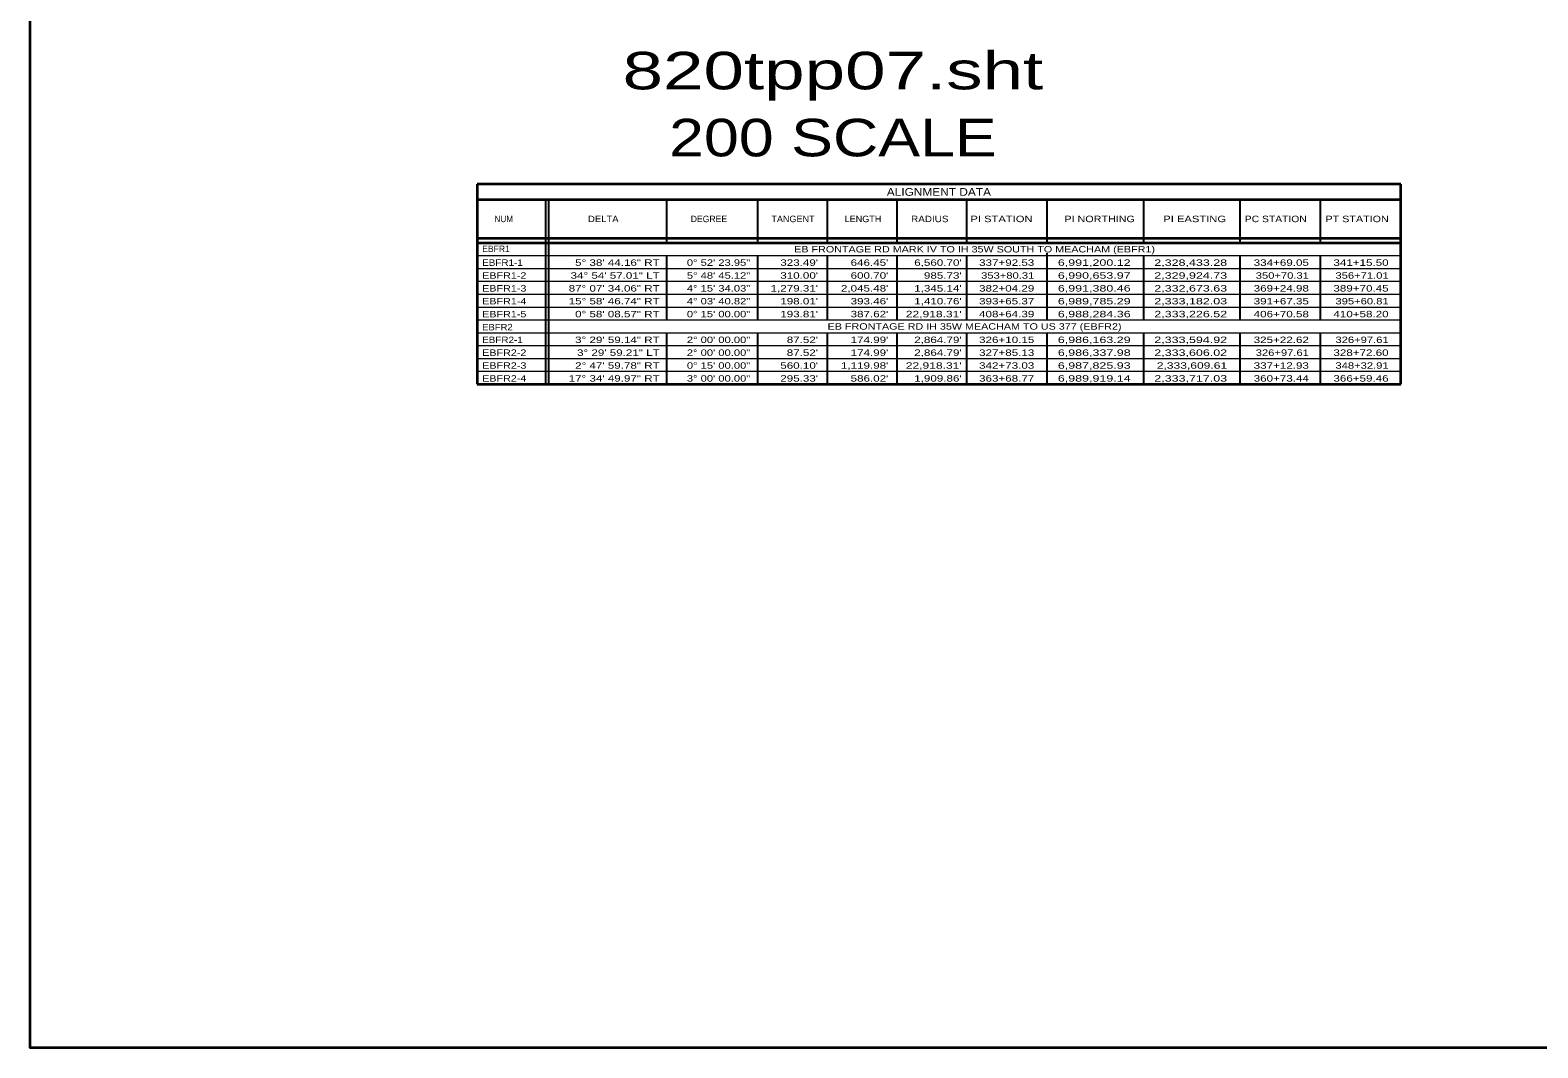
# Model space of a CAD drawing. Extents: x 1953053 to 1967065, y 7363860 to 7371201.
# Drawn here: x 1953053 to 1955866, y 7363860 to 7365759 of the extents above; entities that cross this region are included whole.
import ezdxf
from ezdxf.enums import TextEntityAlignment as Align

# ---------------------------------------------------------------- set-up
doc = ezdxf.new("R2010")
doc.units = 0
doc.header["$LTSCALE"] = 4.8
doc.layers.add('10', color=7, linetype='Continuous')
doc.layers.add('12', color=7, linetype='Continuous', lineweight=25)
doc.layers.add('62', color=7, linetype='Continuous', lineweight=35)

msp = doc.modelspace()

# ---------------------------------------------------------------- linework, layer by layer
at = {"layer": '12', "lineweight": 35}
for p, q in [((1955609.815, 7365471.266), (1953886.483, 7365471.266)), ((1953886.483, 7365471.266), (1953886.483, 7365098.133)), ((1955609.815, 7365098.133), (1955609.815, 7365471.266)), ((1953886.483, 7365442.466), (1955609.815, 7365442.466)), ((1953886.483, 7365370.466), (1955609.815, 7365370.466)), ((1953886.483, 7365362.133), (1955609.815, 7365362.133)), ((1953886.483, 7365098.133), (1955609.815, 7365098.133))]:
    msp.add_line(p, q, dxfattribs=at)
at = {"layer": '12'}
for p, q in [((1954014.328, 7365442.466), (1954014.328, 7365098.133)), ((1954019.815, 7365442.466), (1954019.815, 7365098.133)), ((1954239.815, 7365442.466), (1954239.815, 7365362.133)), ((1954409.815, 7365442.466), (1954409.815, 7365362.133)), ((1954539.815, 7365442.466), (1954539.815, 7365362.133)), ((1954669.815, 7365442.466), (1954669.815, 7365362.133)), ((1954799.815, 7365442.466), (1954799.815, 7365362.133)), ((1954949.815, 7365442.466), (1954949.815, 7365362.133)), ((1955129.815, 7365442.466), (1955129.815, 7365362.133)), ((1955309.815, 7365442.466), (1955309.815, 7365362.133)), ((1955459.815, 7365442.466), (1955459.815, 7365362.133)), ((1954014.328, 7365420.866), (1954014.328, 7365144.913)), ((1954239.815, 7365338.133), (1954239.815, 7365218.133)), ((1954409.815, 7365338.133), (1954409.815, 7365218.133)), ((1954539.815, 7365338.133), (1954539.815, 7365218.133)), ((1954669.815, 7365338.133), (1954669.815, 7365218.133)), ((1954799.815, 7365338.133), (1954799.815, 7365218.133)), ((1954949.815, 7365342.393), (1954949.815, 7365218.133)), ((1955129.815, 7365338.133), (1955129.815, 7365218.133)), ((1955309.815, 7365338.133), (1955309.815, 7365218.133)), ((1955459.815, 7365338.133), (1955459.815, 7365218.133)), ((1954239.815, 7365194.133), (1954239.815, 7365098.133)), ((1954409.815, 7365194.133), (1954409.815, 7365098.133)), ((1954539.815, 7365194.133), (1954539.815, 7365098.133)), ((1954669.815, 7365194.133), (1954669.815, 7365098.133)), ((1954799.815, 7365194.133), (1954799.815, 7365098.133)), ((1954949.815, 7365194.133), (1954949.815, 7365098.133)), ((1955129.815, 7365194.133), (1955129.815, 7365098.133)), ((1955309.815, 7365194.133), (1955309.815, 7365098.133)), ((1955459.815, 7365194.133), (1955459.815, 7365098.133))]:
    msp.add_line(p, q, dxfattribs=at)
at = {"layer": '12', "lineweight": 13}
for p, q in [((1953886.483, 7365338.133), (1955609.815, 7365338.133)), ((1953886.483, 7365314.133), (1955609.815, 7365314.133)), ((1953886.483, 7365290.133), (1955609.815, 7365290.133)), ((1953886.483, 7365266.133), (1955609.815, 7365266.133)), ((1953886.483, 7365242.133), (1955609.815, 7365242.133)), ((1953886.483, 7365218.133), (1955609.815, 7365218.133)), ((1953886.483, 7365194.133), (1955609.815, 7365194.133)), ((1953886.483, 7365170.133), (1955609.815, 7365170.133)), ((1953886.483, 7365146.133), (1955609.815, 7365146.133)), ((1953886.483, 7365122.133), (1955609.815, 7365122.133))]:
    msp.add_line(p, q, dxfattribs=at)
at = {"layer": '62'}
msp.add_lwpolyline([(1953052.784, 7371201.108), (1967065.314, 7371201.108), (1967065.314, 7363859.877), (1953052.784, 7363859.877)], close=True, dxfattribs=at)

# ---------------------------------------------------------------- texts
at = {"layer": '10'}
msp.add_text('EBFR1', height=12, dxfattribs=at).set_placement((1953896.104, 7365344.628))
at = {"layer": '10', "width": 1.25}
for s, p in [('EB FRONTAGE RD MARK IV TO IH 35W SOUTH TO MEACHAM (EBFR1)', (1954814.815, 7365343.927)), ('EB FRONTAGE RD IH 35W MEACHAM TO US 377 (EBFR2)', (1954814.815, 7365199.927))]:
    msp.add_text(s, height=12, dxfattribs=at).set_placement(p, align=Align.CENTER)
at = {"layer": '10'}
for s, width, p in [('EBFR1-1', 1.15, (1953896.104, 7365318.96)), ('EBFR1-2', 1.25, (1953896.104, 7365294.96)), ('EBFR1-3', 1.25, (1953896.104, 7365270.96)), ('EBFR1-4', 1.25, (1953896.104, 7365246.96)), ('EBFR1-5', 1.25, (1953896.104, 7365222.96)), ('EBFR2', 1.1, (1953896.104, 7365198.683)), ('EBFR2-1', 1.15, (1953896.104, 7365174.96)), ('EBFR2-2', 1.25, (1953896.104, 7365150.96)), ('EBFR2-3', 1.25, (1953896.104, 7365126.96)), ('EBFR2-4', 1.25, (1953896.104, 7365102.96))]:
    msp.add_text(s, height=12, dxfattribs=dict(at, width=width)).set_placement(p)
for s, width, p in [('5° 38\' 44.16" RT', 1.35, (1954227.337, 7365318.96)), ('0° 52\' 23.95"', 1.3, (1954396.332, 7365318.96)), ("323.49'", 1.35, (1954522.742, 7365318.96)), ("646.45'", 1.35, (1954653.939, 7365318.96)), ("6,560.70'", 1.35, (1954790.708, 7365318.96)), ('337+92.53', 1.35, (1954926.252, 7365318.96)), ('6,991,200.12', 1.45, (1955106.017, 7365318.96)), ('2,328,433.28', 1.45, (1955286.017, 7365318.96)), ('334+69.05', 1.35, (1955438.595, 7365318.96)), ('341+15.50', 1.35, (1955587.327, 7365318.96)), ('34° 54\' 57.01" LT', 1.35, (1954227.337, 7365294.96)), ('5° 48\' 45.12"', 1.3, (1954396.332, 7365294.96)), ("310.00'", 1.35, (1954522.742, 7365294.96)), ("600.70'", 1.35, (1954653.939, 7365294.96)), ("985.73'", 1.35, (1954790.708, 7365294.96)), ('353+80.31', 1.3, (1954926.252, 7365294.96)), ('6,990,653.97', 1.45, (1955106.017, 7365294.96)), ('2,329,924.73', 1.45, (1955286.017, 7365294.96)), ('350+70.31', 1.3, (1955438.595, 7365294.96)), ('356+71.01', 1.3, (1955587.327, 7365294.96)), ('87° 07\' 34.06" RT', 1.35, (1954227.337, 7365270.96)), ('4° 15\' 34.03"', 1.3, (1954396.332, 7365270.96)), ("1,279.31'", 1.35, (1954522.742, 7365270.96)), ("2,045.48'", 1.35, (1954653.939, 7365270.96)), ("1,345.14'", 1.35, (1954790.708, 7365270.96)), ('382+04.29', 1.35, (1954926.252, 7365270.96)), ('6,991,380.46', 1.45, (1955106.017, 7365270.96)), ('2,332,673.63', 1.45, (1955286.017, 7365270.96)), ('369+24.98', 1.35, (1955438.595, 7365270.96)), ('389+70.45', 1.35, (1955587.327, 7365270.96)), ('15° 58\' 46.74" RT', 1.35, (1954227.337, 7365246.96)), ('0° 58\' 08.57" RT', 1.35, (1954227.337, 7365222.96)), ('4° 03\' 40.82"', 1.3, (1954396.332, 7365246.96)), ('0° 15\' 00.00"', 1.3, (1954396.332, 7365222.96)), ("198.01'", 1.35, (1954522.742, 7365246.96)), ("193.81'", 1.35, (1954522.742, 7365222.96)), ("393.46'", 1.35, (1954653.939, 7365246.96)), ("387.62'", 1.35, (1954653.939, 7365222.96)), ("22,918.31'", 1.4, (1954790.708, 7365222.96)), ("1,410.76'", 1.35, (1954790.708, 7365246.96)), ('408+64.39', 1.35, (1954926.252, 7365222.96)), ('393+65.37', 1.35, (1954926.252, 7365246.96)), ('6,989,785.29', 1.45, (1955106.017, 7365246.96)), ('6,988,284.36', 1.45, (1955106.017, 7365222.96)), ('2,333,182.03', 1.45, (1955286.017, 7365246.96)), ('2,333,226.52', 1.45, (1955286.017, 7365222.96)), ('406+70.58', 1.35, (1955438.595, 7365222.96)), ('391+67.35', 1.35, (1955438.595, 7365246.96)), ('410+58.20', 1.35, (1955587.327, 7365222.96)), ('395+60.81', 1.3, (1955587.327, 7365246.96)), ('3° 29\' 59.14" RT', 1.35, (1954227.337, 7365174.96)), ('2° 00\' 00.00"', 1.3, (1954396.332, 7365174.96)), ("87.52'", 1.35, (1954522.742, 7365174.96)), ("174.99'", 1.35, (1954653.939, 7365174.96)), ("2,864.79'", 1.35, (1954790.708, 7365174.96)), ('326+10.15', 1.35, (1954926.252, 7365174.96)), ('6,986,163.29', 1.45, (1955106.017, 7365174.96)), ('2,333,594.92', 1.45, (1955286.017, 7365174.96)), ('325+22.62', 1.35, (1955438.595, 7365174.96)), ('326+97.61', 1.3, (1955587.327, 7365174.96)), ('3° 29\' 59.21" LT', 1.35, (1954227.337, 7365150.96)), ('2° 00\' 00.00"', 1.3, (1954396.332, 7365150.96)), ("87.52'", 1.35, (1954522.742, 7365150.96)), ("174.99'", 1.35, (1954653.939, 7365150.96)), ("2,864.79'", 1.35, (1954790.708, 7365150.96)), ('327+85.13', 1.35, (1954926.252, 7365150.96)), ('6,986,337.98', 1.45, (1955106.017, 7365150.96)), ('2,333,606.02', 1.45, (1955286.017, 7365150.96)), ('326+97.61', 1.3, (1955438.595, 7365150.96)), ('328+72.60', 1.35, (1955587.327, 7365150.96)), ('2° 47\' 59.78" RT', 1.35, (1954227.337, 7365126.96)), ('0° 15\' 00.00"', 1.3, (1954396.332, 7365126.96)), ("560.10'", 1.35, (1954522.742, 7365126.96)), ("1,119.98'", 1.35, (1954653.939, 7365126.96)), ("22,918.31'", 1.4, (1954790.708, 7365126.96)), ('342+73.03', 1.35, (1954926.252, 7365126.96)), ('6,987,825.93', 1.45, (1955106.017, 7365126.96)), ('2,333,609.61', 1.4, (1955286.017, 7365126.96)), ('337+12.93', 1.35, (1955438.595, 7365126.96)), ('348+32.91', 1.3, (1955587.327, 7365126.96)), ('17° 34\' 49.97" RT', 1.35, (1954227.337, 7365102.96)), ('3° 00\' 00.00"', 1.3, (1954396.332, 7365102.96)), ("295.33'", 1.35, (1954522.742, 7365102.96)), ("586.02'", 1.35, (1954653.939, 7365102.96)), ("1,909.86'", 1.35, (1954790.708, 7365102.96)), ('363+68.77', 1.35, (1954926.252, 7365102.96)), ('6,989,919.14', 1.45, (1955106.017, 7365102.96)), ('2,333,717.03', 1.45, (1955286.017, 7365102.96)), ('360+73.44', 1.35, (1955438.595, 7365102.96)), ('366+59.46', 1.35, (1955587.327, 7365102.96))]:
    msp.add_text(s, height=12, dxfattribs=dict(at, width=width)).set_placement(p, align=Align.RIGHT)
at = {"layer": '12'}
for s, height, width, p in [('ALIGNMENT DATA', 14.4, 1.15, (1954748.256, 7365449.665)), ('NUM', 12, 0.95, (1953936.529, 7365400.462)), ('DELTA', 12, 1.1, (1954122.106, 7365400.465)), ('TANGENT', 12, 1.05, (1954476.003, 7365400.465)), ('LENGTH', 12, 1.05, (1954606.638, 7365400.465)), ('RADIUS', 12, 1.15, (1954731.248, 7365400.465)), ('PI STATION', 12, 1.3, (1954865.052, 7365400.465)), ('PI NORTHING', 12, 1.25, (1955048.127, 7365400.465)), ('PI EASTING', 12, 1.3, (1955225.519, 7365400.465)), ('PC STATION', 12, 1.2, (1955376.824, 7365400.465)), ('PT STATION', 12, 1.25, (1955528.595, 7365400.465))]:
    msp.add_text(s, height=height, dxfattribs=dict(at, width=width)).set_placement(p, align=Align.CENTER)
msp.add_text('DEGREE', height=12, dxfattribs=at).set_placement((1954319.192, 7365400.465), align=Align.CENTER)
at = {"layer": '62'}
for s, width, p in [('820tpp07.sht', 1.45, (1954550.539, 7365648.265)), ('200 SCALE', 1.25, (1954550.539, 7365523.265))]:
    msp.add_text(s, height=70, dxfattribs=dict(at, width=width)).set_placement(p, align=Align.CENTER)

doc.saveas('drawing.dxf')
